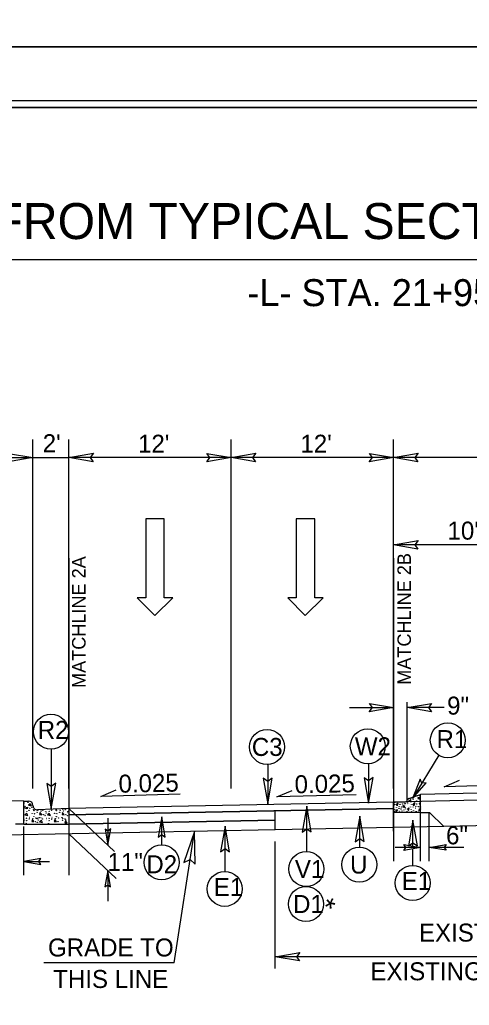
# Model space of a CAD drawing. Extents: x 2320980 to 2456309, y 595047 to 606177.
# Drawn here: x 2455845 to 2455878.3, y 597108.7 to 597181.6 of the extents above; entities that cross this region are included whole.
import ezdxf

# ---------------------------------------------------------------- set-up
doc = ezdxf.new("R2010")
doc.units = 0
for name, color, linetype in [('Matchline', 7, 'Continuous'), ('Matchline Text', 7, 'Continuous'), ('Old_Level_1', 7, 'Continuous'), ('Old_Level_11', 7, 'Continuous'), ('Old_Level_2', 7, 'Continuous'), ('Old_Level_20', 7, 'Continuous'), ('Old_Level_21', 7, 'Continuous'), ('Old_Level_3', 7, 'Continuous'), ('Prop Dimension', 7, 'Continuous'), ('Prop Dimension Text', 7, 'Continuous'), ('Prop Lane Arrow CELL', 7, 'Continuous'), ('Prop Terminator CELL', 7, 'Continuous'), ('Sheet Cutting Line CELL', 7, 'Continuous'), ('Sheet Plan CELL', 7, 'Continuous'), ('Sheet Plot Border Inside CELL', 7, 'Continuous'), ('Sheet Plot Border Outside CELL', 7, 'Continuous'), ('Typical Berm CELL', 7, 'Continuous'), ('Typical Curb CELL', 7, 'Continuous'), ('Typical ID Circle CELL', 7, 'Continuous'), ('Typical Pavement Slope CELL', 7, 'Continuous'), ('Typical Pavement Slope Information CELL', 7, 'Continuous'), ('Typical Terminator CELL', 7, 'Continuous')]:
    doc.layers.add(name, color=color, linetype=linetype)

msp = doc.modelspace()

# ---------------------------------------------------------------- linework, layer by layer
at = {"layer": 'Matchline'}
for p, q in [((2455848.677, 597141.77), (2455848.677, 597118.337)), ((2455872.677, 597141.77), (2455872.677, 597119.384))]:
    msp.add_line(p, q, dxfattribs=at)
at = {"layer": 'Old_Level_1'}
for p, q in [((2455872.677, 597122.974), (2455872.677, 597123.75)), ((2455873.497, 597123.75), (2455872.677, 597123.75)), ((2455873.807, 597124.016), (2455874.672, 597124.304)), ((2455873.839, 597123.88), (2455873.955, 597123.88)), ((2455873.846, 597123.764), (2455873.839, 597123.88)), ((2455873.955, 597123.88), (2455873.846, 597123.764)), ((2455874.495, 597124.087), (2455874.61, 597124.087)), ((2455874.501, 597123.972), (2455874.495, 597124.087)), ((2455874.61, 597124.087), (2455874.501, 597123.972)), ((2455874.672, 597122.974), (2455874.672, 597124.304)), ((2455863.927, 597121.7), (2455863.927, 597123.094)), ((2455874.672, 597122.974), (2455872.677, 597122.974)), ((2455872.86, 597123.167), (2455872.976, 597123.167)), ((2455872.867, 597123.051), (2455872.86, 597123.167)), ((2455872.976, 597123.167), (2455872.867, 597123.051)), ((2455872.883, 597123.581), (2455872.993, 597123.659)), ((2455872.937, 597123.46), (2455872.883, 597123.581)), ((2455872.993, 597123.659), (2455872.937, 597123.46)), ((2455873.379, 597123.488), (2455873.476, 597123.469)), ((2455873.427, 597123.323), (2455873.379, 597123.488)), ((2455873.476, 597123.469), (2455873.427, 597123.323)), ((2455873.815, 597123.292), (2455873.694, 597123.226)), ((2455873.694, 597123.226), (2455873.773, 597123.116)), ((2455873.773, 597123.116), (2455873.815, 597123.292)), ((2455874.118, 597123.602), (2455874.229, 597123.68)), ((2455874.173, 597123.48), (2455874.118, 597123.602)), ((2455874.229, 597123.68), (2455874.173, 597123.48)), ((2455874.575, 597123.256), (2455874.672, 597123.237)), ((2455874.622, 597123.091), (2455874.575, 597123.256)), ((2455874.672, 597123.237), (2455874.622, 597123.091)), ((2455872.677, 597121.874), (2455863.927, 597121.7)), ((2455883.427, 597122.089), (2455876.374, 597121.948))]:
    msp.add_line(p, q, dxfattribs=at)
for centre in [(2455872.745, 597123.708), (2455872.981, 597123.733), (2455873.357, 597123.745), (2455873.751, 597123.865), (2455873.937, 597123.979), (2455873.961, 597123.76), (2455874.119, 597123.948), (2455874.199, 597124.113), (2455874.216, 597123.754), (2455874.317, 597124.035), (2455874.374, 597123.821), (2455874.411, 597124.203), (2455874.593, 597123.766), (2455874.602, 597124.187), (2455874.637, 597123.898), (2455872.689, 597123.368), (2455872.732, 597123.186), (2455872.75, 597123.022), (2455872.756, 597123.557), (2455872.884, 597123.362), (2455872.962, 597122.99), (2455873.066, 597123.277), (2455873.084, 597123.405), (2455873.102, 597123.047), (2455873.145, 597123.581), (2455873.216, 597123.231), (2455873.266, 597123.387), (2455873.285, 597123.001), (2455873.297, 597123.101), (2455873.345, 597123.599), (2455873.428, 597123.163), (2455873.503, 597123.605), (2455873.524, 597123.645), (2455873.533, 597123.332), (2455873.555, 597123.226), (2455873.555, 597123.019), (2455873.658, 597123.037), (2455873.676, 597123.541), (2455873.706, 597123.675), (2455873.87, 597123.639), (2455873.925, 597123.389), (2455873.967, 597123.207), (2455873.986, 597123.043), (2455873.992, 597123.578), (2455874.119, 597123.383), (2455874.142, 597123.116), (2455874.263, 597123.001), (2455874.301, 597123.298), (2455874.32, 597123.426), (2455874.338, 597123.068), (2455874.38, 597123.602), (2455874.502, 597123.408), (2455874.532, 597123.122), (2455874.581, 597123.62), (2455874.642, 597123.386)]:
    msp.add_circle(centre, 0.00853, dxfattribs=at)
for centre, radius, start, end in [((2455873.497, 597123.944), 0.194, 270, 343.28105), ((2455873.869, 597123.832), 0.194, 108.43495, 163.28105), ((2455874.647, 597122.983), 0.00853, 25.75843, 152.96144)]:
    msp.add_arc(centre, radius, start, end, dxfattribs=at)
at = {"layer": 'Old_Level_11'}
msp.add_lwpolyline([(2455857.997, 597119.151), (2455857.958, 597121.58), (2455857.166, 597119.267), (2455857.634, 597119.504)], close=True, dxfattribs=at)
at = {"layer": 'Old_Level_21'}
for p, q in [((2455846.017, 597140.832), (2455846.017, 597150.539)), ((2455848.677, 597124.75), (2455848.677, 597150.539)), ((2455860.677, 597124.75), (2455860.677, 597150.539)), ((2455872.677, 597124.75), (2455872.677, 597150.539)), ((2455836.017, 597149.209), (2455848.677, 597149.209)), ((2455874.117, 597149.209), (2455848.677, 597149.209)), ((2455894.177, 597149.209), (2455872.677, 597149.209)), ((2455883.427, 597142.75), (2455872.677, 597142.75)), ((2455846.017, 597124.75), (2455846.017, 597140.832)), ((2455873.674, 597123.921), (2455873.674, 597131.141)), ((2455869.401, 597130.725), (2455872.677, 597130.725)), ((2455876.404, 597130.725), (2455873.674, 597130.725)), ((2455874.672, 597119.384), (2455874.672, 597122.974)), ((2455875.305, 597119.384), (2455875.305, 597122.928)), ((2455845.352, 597118.337), (2455845.352, 597121.928)), ((2455856.444, 597111.866), (2455857.958, 597121.58)), ((2455863.927, 597111.437), (2455863.927, 597120.835)), ((2455903.112, 597112.315), (2455863.927, 597112.315)), ((2455856.444, 597111.866), (2455846.825, 597111.866))]:
    msp.add_line(p, q, dxfattribs=at)
at = {"layer": 'Old_Level_3'}
for p, q in [((2455820.86, 597163.852), (2455948.687, 597163.852)), ((2455872.677, 597123.267), (2455848.677, 597122.793)), ((2455863.927, 597122.415), (2455848.677, 597122.114))]:
    msp.add_line(p, q, dxfattribs=at)
at = {"layer": 'Prop Dimension'}
for p, q in [((2455848.677, 597123.268), (2455852.054, 597120.085)), ((2455851.553, 597122.556), (2455851.553, 597120.556)), ((2455848.675, 597121.391), (2455852.18, 597118.089)), ((2455851.552, 597118.68), (2455851.552, 597116.429))]:
    msp.add_line(p, q, dxfattribs=at)
at = {"layer": 'Prop Dimension Text'}
for p, q in [((2455876.009, 597127.211), (2455874.079, 597124.022)), ((2455855.534, 597120.577), (2455855.534, 597122.659)), ((2455874.672, 597120.396), (2455872.785, 597120.396)), ((2455877.867, 597120.396), (2455875.305, 597120.396)), ((2455845.352, 597119.35), (2455847.239, 597119.35))]:
    msp.add_line(p, q, dxfattribs=at)
for points in [[(2455882.256, 597125.044), (2455876.4, 597124.883), (2455877.537, 597125.372)], [(2455856.887, 597124.33), (2455851.031, 597124.169), (2455852.168, 597124.657)], [(2455869.9, 597124.286), (2455864.044, 597124.125), (2455865.181, 597124.613)]]:
    msp.add_lwpolyline(points, dxfattribs=at)
for centre in [(2455847.351, 597128.944), (2455876.679, 597128.317), (2455863.321, 597127.821), (2455870.767, 597127.867), (2455855.534, 597119.284), (2455866.224, 597118.795), (2455870.146, 597119.127), (2455860.196, 597117.33), (2455874.078, 597117.771), (2455866.194, 597116.21)]:
    msp.add_circle(centre, 1.293, dxfattribs=at)
at = {"layer": 'Prop Lane Arrow CELL'}
for p, q in [((2455854.354, 597144.671), (2455854.354, 597138.852)), ((2455855.725, 597144.671), (2455854.354, 597144.671)), ((2455855.725, 597138.852), (2455855.725, 597144.671)), ((2455865.472, 597144.671), (2455865.472, 597138.852)), ((2455866.843, 597144.671), (2455865.472, 597144.671)), ((2455866.843, 597138.852), (2455866.843, 597144.671)), ((2455854.354, 597138.852), (2455853.73, 597138.852)), ((2455853.73, 597138.852), (2455855.019, 597137.543)), ((2455855.019, 597137.543), (2455856.349, 597138.852)), ((2455856.349, 597138.852), (2455855.725, 597138.852)), ((2455865.472, 597138.852), (2455864.848, 597138.852)), ((2455864.848, 597138.852), (2455866.137, 597137.543)), ((2455866.137, 597137.543), (2455867.467, 597138.852)), ((2455867.467, 597138.852), (2455866.843, 597138.852))]:
    msp.add_line(p, q, dxfattribs=at)
at = {"layer": 'Prop Terminator CELL'}
for points in [[(2455851.347, 597121.753), (2455851.553, 597120.556), (2455851.766, 597121.76), (2455851.553, 597121.607)], [(2455851.758, 597117.483), (2455851.552, 597118.68), (2455851.339, 597117.477), (2455851.552, 597117.63)]]:
    msp.add_lwpolyline(points, close=True, dxfattribs=at)
at = {"layer": 'Sheet Cutting Line CELL'}
msp.add_line((2456045.507, 597179.574), (2455708.807, 597179.574), dxfattribs=at)
at = {"layer": 'Sheet Plan CELL'}
for points in [[(2455742.104, 596965.076), (2455742.099, 597175.071), (2456002.097, 597175.079), (2456002.099, 597145.066), (2456042.107, 597145.064), (2456042.107, 596965.076)], [(2456042.112, 597175.076), (2455742.104, 597175.076), (2455742.104, 596965.076), (2456042.107, 596965.076)]]:
    msp.add_lwpolyline(points, close=True, dxfattribs=at)
at = {"layer": 'Sheet Plot Border Inside CELL'}
msp.add_lwpolyline([(2455711.407, 596964.574), (2456044.604, 596964.576), (2456044.607, 597175.574), (2455711.407, 597175.574)], close=True, dxfattribs=at)
at = {"layer": 'Sheet Plot Border Outside CELL'}
for points in [[(2455708.807, 597179.574), (2456045.507, 597179.574), (2456045.507, 597398.574), (2455708.807, 597398.574)], [(2455708.807, 596960.574), (2456045.507, 596960.574), (2456045.507, 597179.574), (2455708.807, 597179.574)]]:
    msp.add_lwpolyline(points, close=True, dxfattribs=at)
at = {"layer": 'Typical Berm CELL'}
for p, q in [((2455845.352, 597123.822), (2455836.017, 597124.016)), ((2455845.352, 597122.105), (2455844.729, 597122.105))]:
    msp.add_line(p, q, dxfattribs=at)
at = {"layer": 'Typical Curb CELL'}
for p, q in [((2455845.352, 597122.105), (2455845.352, 597123.822)), ((2455845.352, 597123.822), (2455845.698, 597123.822)), ((2455845.401, 597123.319), (2455845.606, 597123.378)), ((2455845.584, 597123.258), (2455845.401, 597123.319)), ((2455845.606, 597123.378), (2455845.584, 597123.258)), ((2455845.82, 597123.622), (2455845.683, 597123.522)), ((2455845.683, 597123.522), (2455845.903, 597123.469)), ((2455845.903, 597123.469), (2455845.82, 597123.622)), ((2455846.017, 597123.489), (2455846.017, 597123.503)), ((2455848.677, 597123.268), (2455846.349, 597123.171)), ((2455846.555, 597122.97), (2455846.509, 597122.819)), ((2455846.668, 597122.81), (2455846.555, 597122.97)), ((2455848.215, 597122.97), (2455848.17, 597122.819)), ((2455848.33, 597122.81), (2455848.215, 597122.97)), ((2455845.568, 597122.895), (2455845.431, 597122.795)), ((2455845.431, 597122.795), (2455845.651, 597122.743)), ((2455845.651, 597122.743), (2455845.568, 597122.895)), ((2455845.977, 597122.46), (2455845.931, 597122.309)), ((2455845.931, 597122.309), (2455846.09, 597122.301)), ((2455846.09, 597122.301), (2455845.977, 597122.46)), ((2455846.509, 597122.819), (2455846.668, 597122.81)), ((2455846.651, 597122.386), (2455846.514, 597122.286)), ((2455846.514, 597122.286), (2455846.735, 597122.233)), ((2455846.735, 597122.233), (2455846.651, 597122.386)), ((2455847.229, 597122.895), (2455847.092, 597122.795)), ((2455847.092, 597122.795), (2455847.312, 597122.743)), ((2455847.312, 597122.743), (2455847.229, 597122.895)), ((2455847.638, 597122.46), (2455847.592, 597122.309)), ((2455847.592, 597122.309), (2455847.753, 597122.301)), ((2455847.753, 597122.301), (2455847.638, 597122.46)), ((2455848.17, 597122.819), (2455848.33, 597122.81)), ((2455848.427, 597122.369), (2455848.381, 597122.218)), ((2455848.542, 597122.21), (2455848.427, 597122.369)), ((2455845.352, 597122.105), (2455848.677, 597122.105)), ((2455848.381, 597122.218), (2455848.542, 597122.21))]:
    msp.add_line(p, q, dxfattribs=at)
for centre in [(2455845.658, 597123.721), (2455845.37, 597123.675), (2455845.438, 597123.432), (2455845.567, 597123.069), (2455845.727, 597123.136), (2455845.785, 597123.281), (2455845.944, 597123.348), (2455846.069, 597123.174), (2455846.091, 597123.107), (2455846.327, 597122.993), (2455846.365, 597123.129), (2455846.623, 597123.077), (2455846.752, 597123.134), (2455846.896, 597123.024), (2455846.971, 597123.069), (2455847.229, 597123.069), (2455847.388, 597123.136), (2455847.73, 597123.174), (2455847.753, 597123.107), (2455847.988, 597122.993), (2455848.026, 597123.129), (2455848.223, 597123.212), (2455848.284, 597123.077), (2455848.413, 597123.189), (2455848.557, 597123.024), (2455848.632, 597123.069), (2455845.384, 597122.408), (2455845.545, 597122.553), (2455845.552, 597122.37), (2455845.749, 597122.484), (2455845.772, 597122.606), (2455845.962, 597122.917), (2455846.008, 597122.523), (2455846.084, 597122.674), (2455846.129, 597122.879), (2455846.212, 597122.302), (2455846.236, 597122.56), (2455846.318, 597122.514), (2455846.34, 597122.241), (2455846.393, 597122.56), (2455846.416, 597122.431), (2455846.509, 597122.591), (2455846.651, 597122.56), (2455846.721, 597122.5), (2455846.79, 597122.811), (2455846.918, 597122.75), (2455846.993, 597122.94), (2455847.001, 597122.53), (2455847.046, 597122.408), (2455847.206, 597122.553), (2455847.213, 597122.37), (2455847.41, 597122.484), (2455847.434, 597122.606), (2455847.623, 597122.917), (2455847.669, 597122.523), (2455847.745, 597122.674), (2455847.79, 597122.879), (2455847.873, 597122.302), (2455847.897, 597122.56), (2455848.17, 597122.591), (2455848.2, 597122.392), (2455848.223, 597122.515), (2455848.383, 597122.5), (2455848.451, 597122.811), (2455848.458, 597122.431), (2455848.579, 597122.75), (2455848.655, 597122.94), (2455848.662, 597122.53), (2455845.506, 597122.165), (2455847.167, 597122.165)]:
    msp.add_circle(centre, 0.0107, dxfattribs=at)
for centre, start, end in [((2455845.699, 597123.503), 0, 90), ((2455846.336, 597123.489), 180, 272.38446)]:
    msp.add_arc(centre, 0.319, start, end, dxfattribs=at)
at = {"layer": 'Typical ID Circle CELL'}
for p, q in [((2455847.362, 597127.652), (2455847.362, 597123.235)), ((2455863.371, 597126.548), (2455863.371, 597123.608)), ((2455870.818, 597126.595), (2455870.818, 597123.654)), ((2455866.25, 597120.093), (2455866.25, 597123.431)), ((2455870.171, 597120.425), (2455870.171, 597122.716)), ((2455874.103, 597120.536), (2455874.103, 597122.407)), ((2455860.221, 597118.628), (2455860.221, 597121.966)), ((2455874.103, 597119.069), (2455874.103, 597120.251))]:
    msp.add_line(p, q, dxfattribs=at)
at = {"layer": 'Typical Pavement Slope CELL'}
for p, q in [((2455883.427, 597124.5), (2455874.672, 597124.3)), ((2455872.677, 597123.75), (2455848.677, 597123.268)), ((2455872.677, 597123.75), (2455848.677, 597123.268)), ((2455883.427, 597123.991), (2455872.677, 597123.746)), ((2455872.677, 597121.597), (2455872.677, 597123.75)), ((2455872.677, 597123.267), (2455872.677, 597123.75)), ((2455848.677, 597123.268), (2455848.677, 597122.793)), ((2455848.677, 597122.793), (2455872.677, 597123.267)), ((2455863.927, 597123.094), (2455848.677, 597122.793)), ((2455859.634, 597123.009), (2455848.677, 597122.793)), ((2455863.927, 597123.094), (2455859.732, 597123.011)), ((2455863.927, 597122.415), (2455863.927, 597123.094)), ((2455874.672, 597122.974), (2455875.337, 597122.974)), ((2455875.337, 597122.974), (2455876.374, 597121.948)), ((2455848.677, 597122.793), (2455848.677, 597122.114)), ((2455848.677, 597122.793), (2455848.677, 597122.114)), ((2455848.677, 597122.114), (2455863.927, 597122.415)), ((2455848.677, 597122.114), (2455863.927, 597122.415)), ((2455863.927, 597121.7), (2455843.924, 597121.3)), ((2455876.374, 597121.948), (2455872.677, 597121.874))]:
    msp.add_line(p, q, dxfattribs=at)
msp.add_lwpolyline([(2455859.732, 597123.011), (2455859.634, 597123.009)], dxfattribs=at)
at = {"layer": 'Typical Terminator CELL'}
for points in [[(2455844.221, 597149.518), (2455846.017, 597149.209), (2455844.211, 597148.89), (2455844.441, 597149.209)], [(2455850.472, 597148.9), (2455848.677, 597149.209), (2455850.482, 597149.528), (2455850.253, 597149.209)], [(2455858.881, 597149.518), (2455860.677, 597149.209), (2455858.871, 597148.89), (2455859.101, 597149.209)], [(2455862.472, 597148.9), (2455860.677, 597149.209), (2455862.482, 597149.528), (2455862.253, 597149.209)], [(2455870.881, 597149.518), (2455872.677, 597149.209), (2455870.871, 597148.89), (2455871.101, 597149.209)], [(2455874.472, 597148.9), (2455872.677, 597149.209), (2455874.482, 597149.528), (2455874.253, 597149.209)], [(2455874.472, 597142.441), (2455872.677, 597142.75), (2455874.482, 597143.07), (2455874.253, 597142.75)], [(2455870.881, 597131.034), (2455872.677, 597130.725), (2455870.871, 597130.405), (2455871.101, 597130.725)], [(2455875.47, 597130.415), (2455873.674, 597130.725), (2455875.48, 597131.044), (2455875.25, 597130.725)], [(2455863.045, 597125.503), (2455863.371, 597123.608), (2455863.708, 597125.513), (2455863.371, 597125.271)], [(2455870.491, 597125.549), (2455870.818, 597123.654), (2455871.155, 597125.56), (2455870.818, 597125.318)], [(2455874.633, 597125.435), (2455874.079, 597124.022), (2455875.086, 597125.171), (2455874.759, 597125.145)], [(2455847.036, 597125.13), (2455847.362, 597123.235), (2455847.699, 597125.14), (2455847.362, 597124.898)], [(2455866.576, 597121.536), (2455866.25, 597123.431), (2455865.913, 597121.525), (2455866.25, 597121.767)], [(2455855.791, 597121.163), (2455855.534, 597122.659), (2455855.268, 597121.155), (2455855.534, 597121.346)], [(2455870.498, 597120.821), (2455870.171, 597122.716), (2455869.834, 597120.811), (2455870.171, 597121.053)], [(2455874.43, 597120.512), (2455874.103, 597122.407), (2455873.767, 597120.502), (2455874.103, 597120.744)], [(2455860.548, 597120.071), (2455860.221, 597121.966), (2455859.884, 597120.06), (2455860.221, 597120.302)], [(2455873.425, 597120.611), (2455874.672, 597120.396), (2455873.418, 597120.175), (2455873.577, 597120.396)], [(2455876.551, 597120.181), (2455875.305, 597120.396), (2455876.558, 597120.618), (2455876.399, 597120.396)], [(2455846.599, 597119.564), (2455845.352, 597119.35), (2455846.606, 597119.128), (2455846.446, 597119.35)], [(2455865.723, 597112.006), (2455863.927, 597112.315), (2455865.733, 597112.635), (2455865.503, 597112.315)]]:
    msp.add_lwpolyline(points, close=True, dxfattribs=at)

# ---------------------------------------------------------------- texts
at = {"layer": 'Matchline Text'}
for s, p in [('MATCHLINE 2A', (2455849.908, 597132.18)), ('MATCHLINE 2B', (2455873.955, 597132.417))]:
    msp.add_text(s, height=1, rotation=90, dxfattribs=at).set_placement(p)
at = {"layer": 'Old_Level_2'}
for s, height, p in [('TRANSITION FROM TYPICAL SECTION No. 1 TO TYPICAL SECTION No. 2', 2.66, (2455820.573, 597165.361)), ('-L- STA. 21+95.00 TO 23+45.00', 1.995, (2455861.864, 597160.402))]:
    msp.add_text(s, height=height, dxfattribs=at).set_placement(p)
at = {"layer": 'Old_Level_20'}
for s, p in [('R2', (2455846.373, 597128.415)), ('R1', (2455875.845, 597127.733)), ('C3', (2455862.196, 597127.156)), ('W2', (2455869.809, 597127.202)), ('V1', (2455865.38, 597118.13)), ('U', (2455869.454, 597118.462)), ('E1', (2455859.385, 597116.801)), ('E1', (2455873.267, 597117.242)), ('D1', (2455865.243, 597115.545))]:
    msp.add_text(s, height=1.33, dxfattribs=at).set_placement(p)
msp.add_text('D2', height=1.33, rotation=0.00282, dxfattribs=at).set_placement((2455854.4, 597118.483))
at = {"layer": 'Old_Level_21'}
for s, rotation, p in [("2'", 359.99984, (2455846.74, 597149.605)), ('0.025', 1.14561, (2455852.355, 597124.435)), ('0.025', 1.14561, (2455865.369, 597124.391))]:
    msp.add_text(s, height=1.33, rotation=rotation, dxfattribs=at).set_placement(p)
for s, p in [("12'", (2455853.786, 597149.568)), ("12'", (2455865.786, 597149.568)), ('10\'-3"', (2455876.657, 597143.144)), ('9"', (2455876.625, 597130.21)), ('6"', (2455876.548, 597120.623)), ('EXISTING PAVEMENT', (2455874.546, 597113.432)), ('GRADE TO', (2455847.13, 597112.333)), ('THIS LINE', (2455847.517, 597110.005)), ('EXISTING PAVEMENT (VARIES)', (2455870.958, 597110.573))]:
    msp.add_text(s, height=1.33, dxfattribs=at).set_placement(p)
at = {"layer": 'Typical Pavement Slope CELL'}
msp.add_text('*', height=1.496, rotation=333.43407, dxfattribs=at).set_placement((2455867.151, 597115.45))
at = {"layer": 'Typical Pavement Slope Information CELL'}
msp.add_text('11"', height=1.33, dxfattribs=at).set_placement((2455851.534, 597118.651))

doc.saveas('drawing.dxf')
